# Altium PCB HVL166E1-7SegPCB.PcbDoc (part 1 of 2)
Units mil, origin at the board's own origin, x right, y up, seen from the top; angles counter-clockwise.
Board outline 2300 x 2421 mil, 2 copper layers (Top Layer, Bottom Layer), stack 62 mil thick; 193 components, 200 nets, 656 pads, 241 vias.
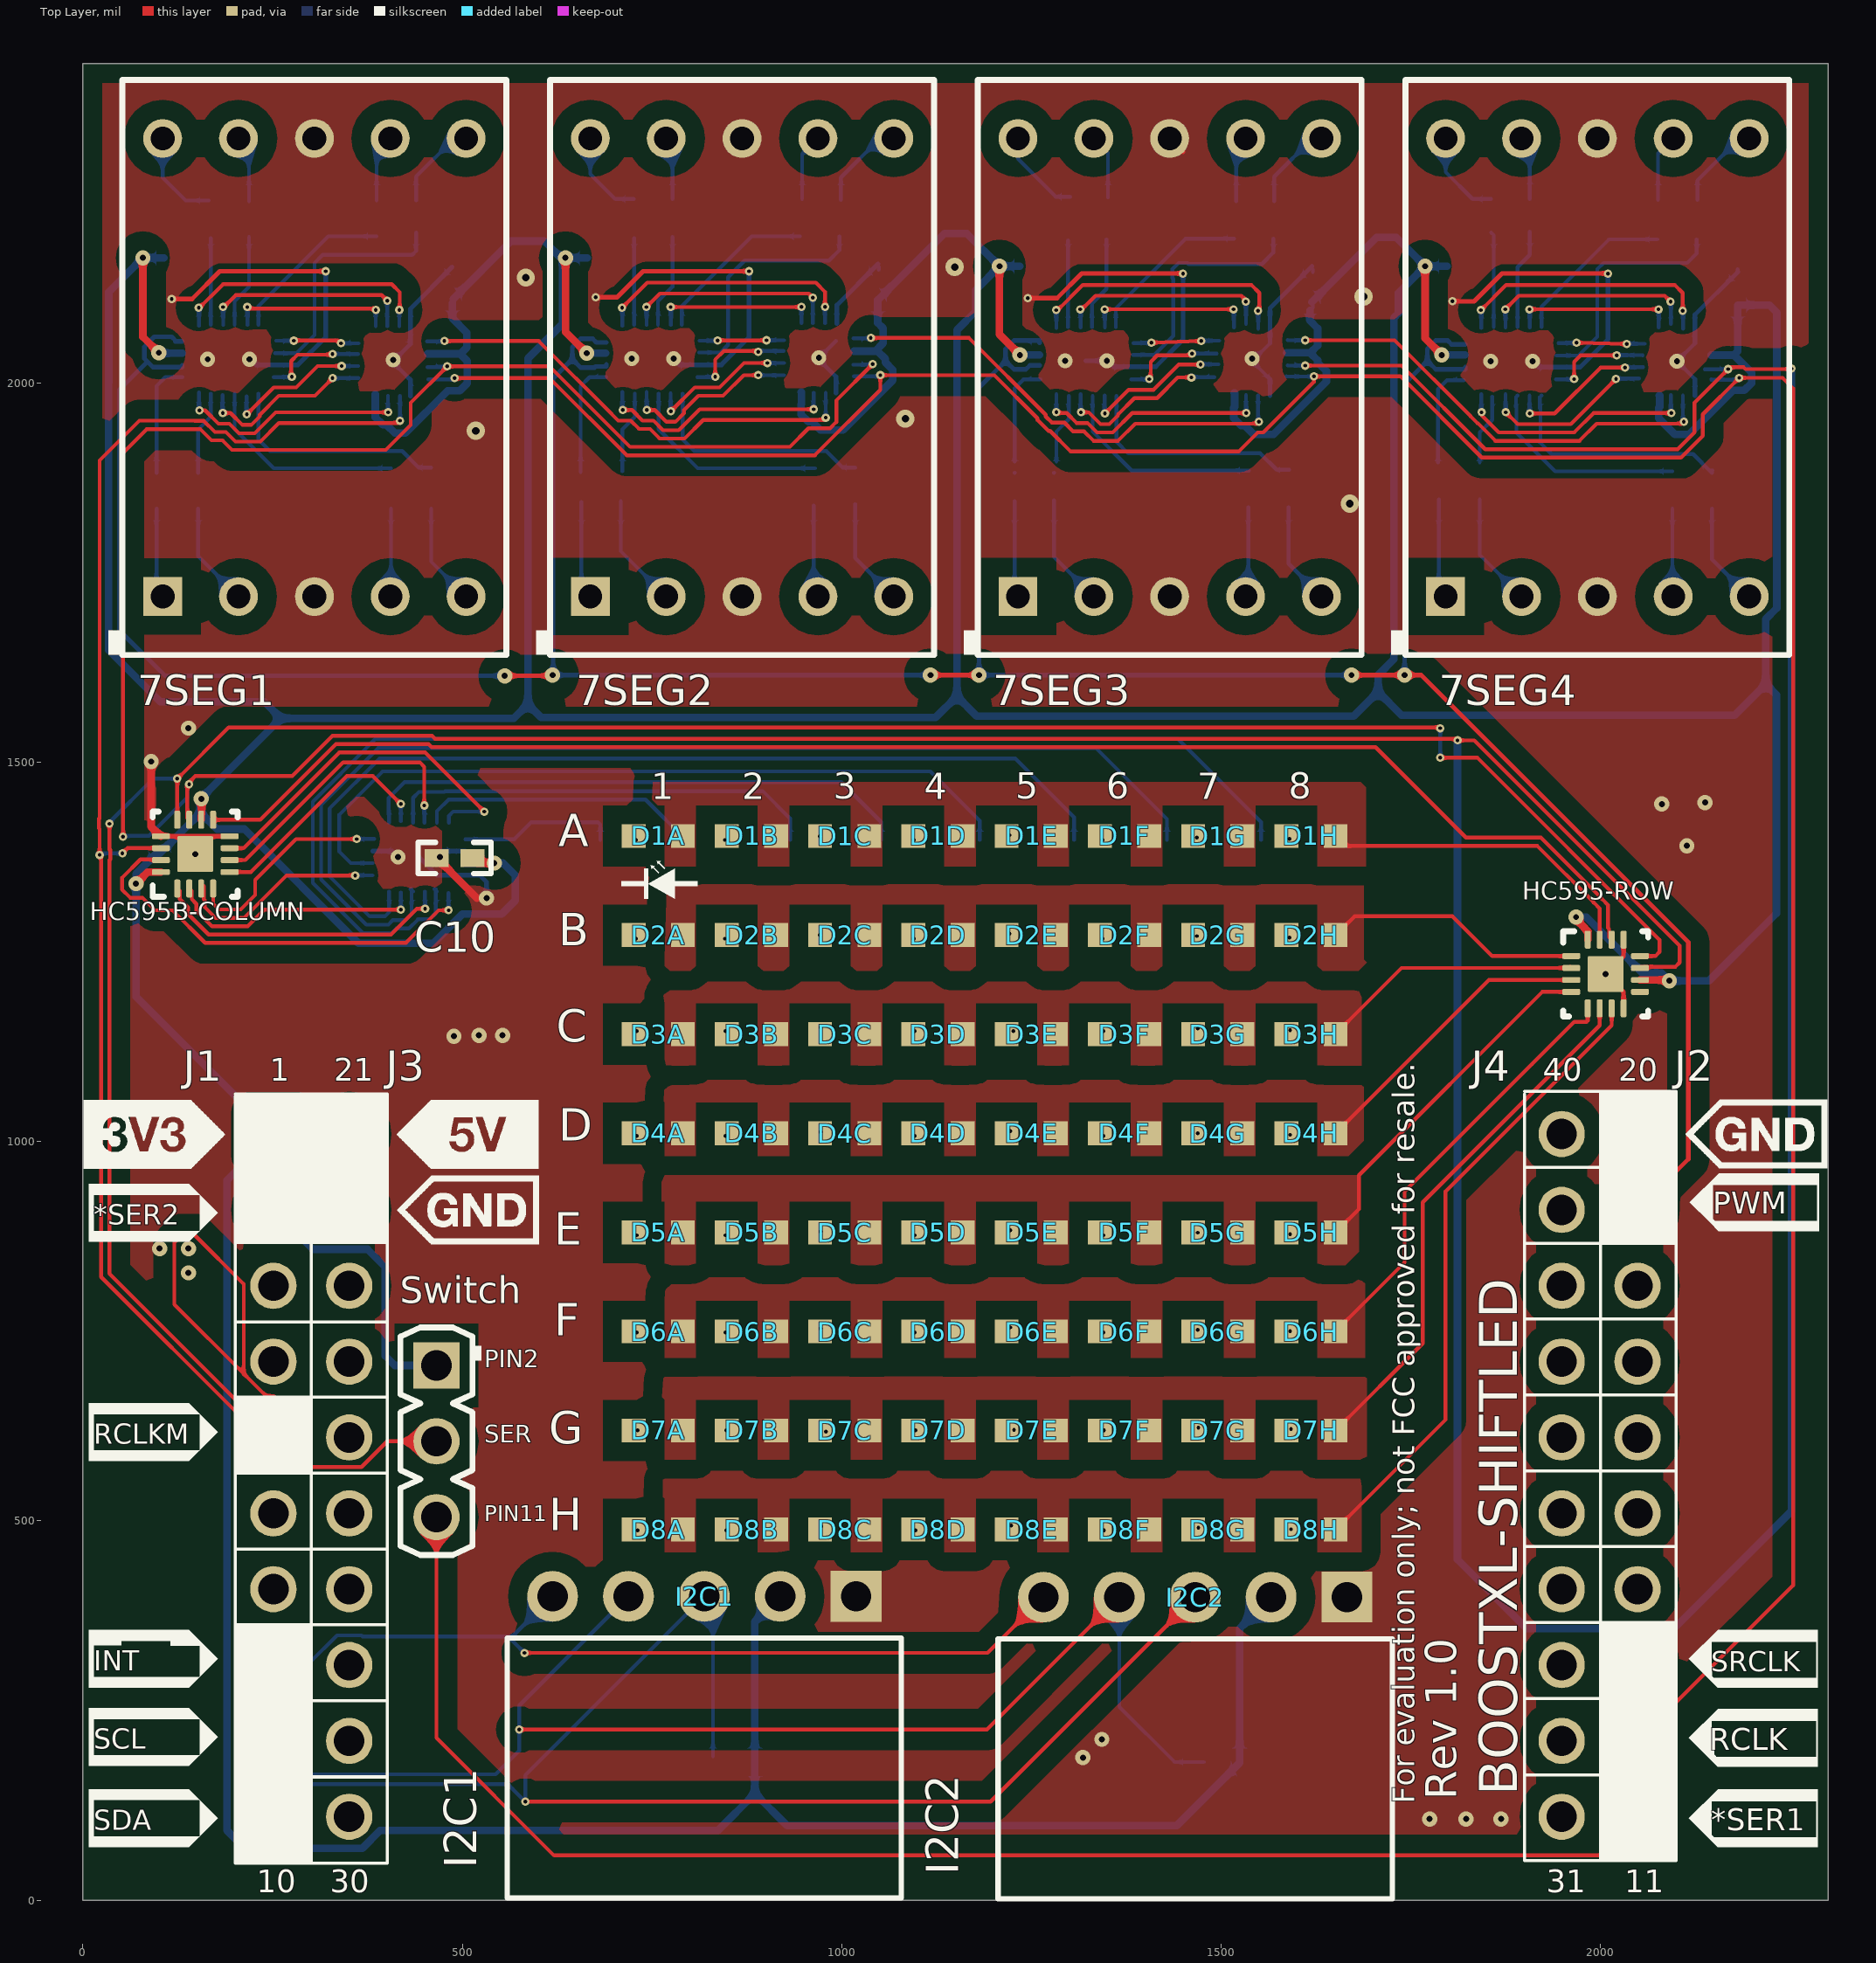
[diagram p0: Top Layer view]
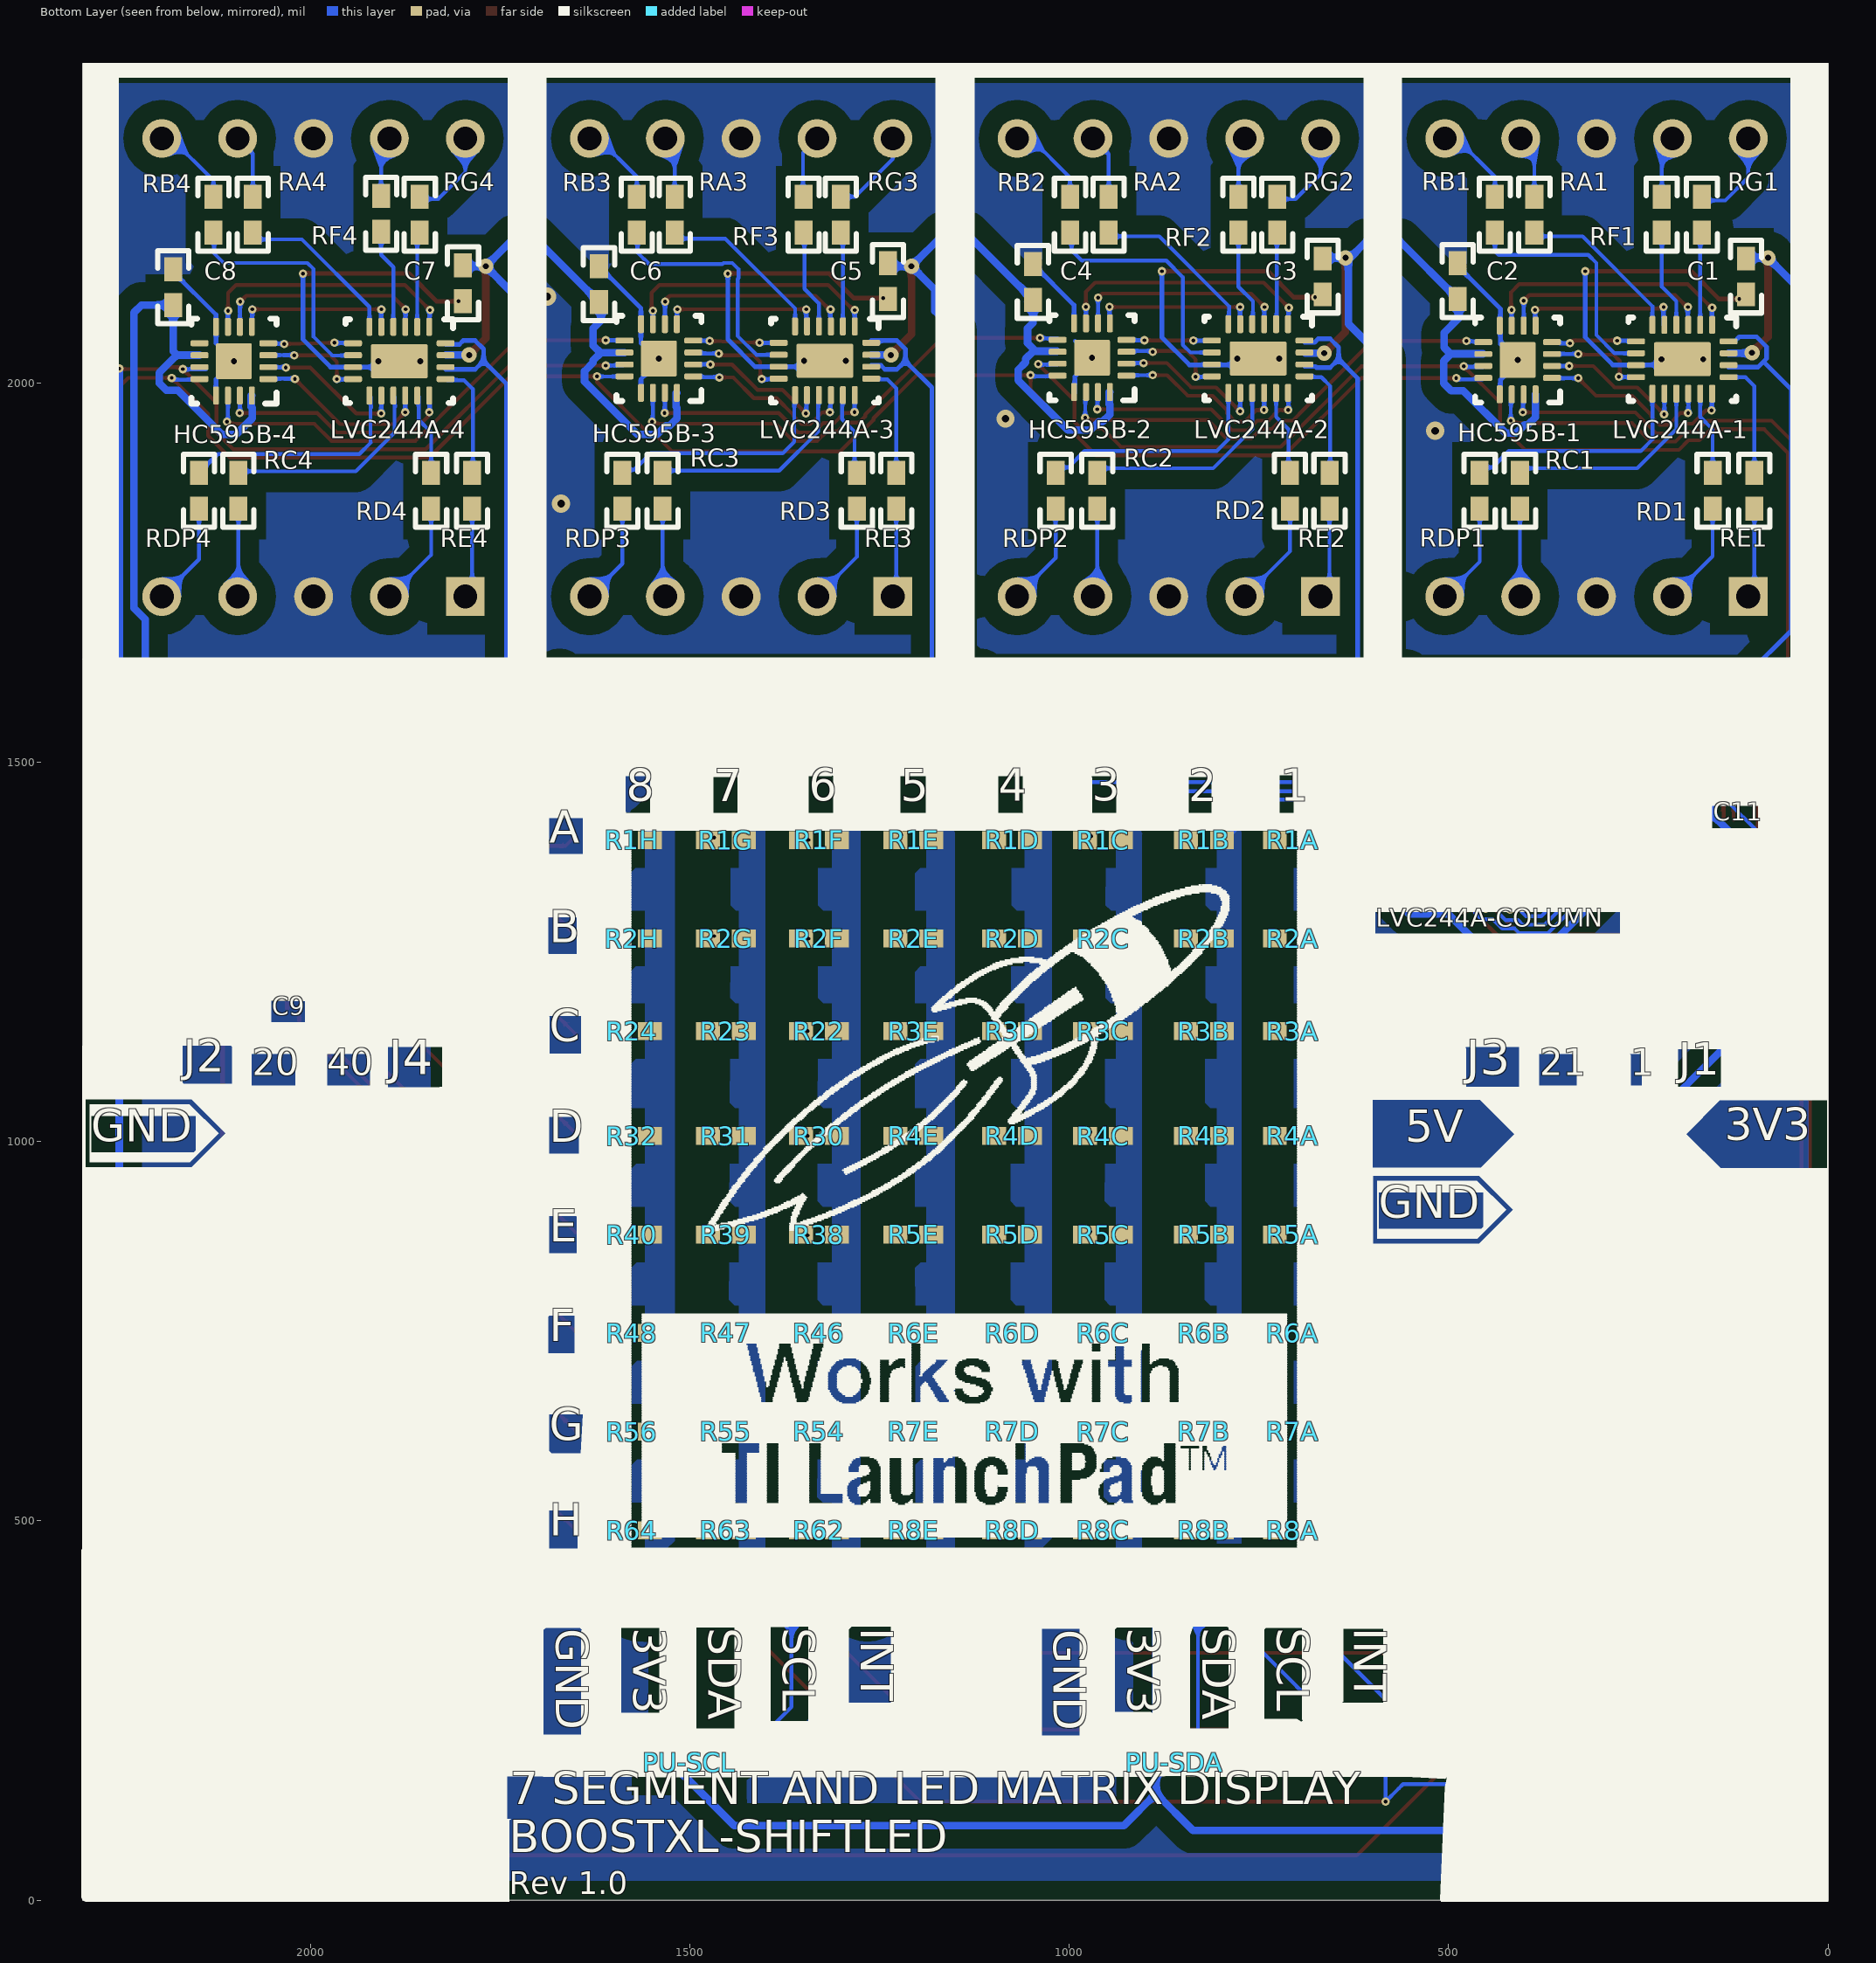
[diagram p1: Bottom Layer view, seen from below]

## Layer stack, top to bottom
Top Solder: solder mask 0.4, Solder Resist, Dk 3.5
Top Layer: signal copper 1.4
Dielectric1: core 59.2, FR-4, Dk 4.8
Bottom Layer: signal copper 1.4
Bottom Solder: solder mask 0.4, Solder Resist, Dk 3.5

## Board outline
0,0 0,2421 2300,2421 2300,0

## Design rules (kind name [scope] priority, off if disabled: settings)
AcuteAngle [All] p1: minimum=4.50000000000000E+0001 checktracksonly=FALSE
AssemblyTestPointUsage [All] p1: valid=2
BoardOutlineClearance BoardOutlineClearance_MountingHoles [OnCopper and InComponentClass('Mounting Holes')] p1: gap=40
BoardOutlineClearance BoardOutlineClearance_Poly [OnCopper and IsPoly] p2: gap=25
BoardOutlineClearance [OnCopper and Not InComponentClass('Logo') and not InComponentClass('FiducialMark') and not InRegion(1000,500,4000,800) and not InPoly] p3: gap=75
Clearance Clearance_Keepouts [((IsTrack Or IsArc) And Not InPoly) And IsFree and IsKeepOut vs ((IsTrack Or IsArc) And Not InPoly) And IsFree and IsKeepOut] p1: gap=0
Clearance Clearance_Poly [InPolygon] p2: gap=25
Clearance [All] p3: gap=6
ComponentClearance ComponentClearance_MountingHoles_FiducialMarks [InComponentClass('Mounting Holes') vs InComponentClass('FiducialMark')] p1: gap=50 collisioncheckmode=3 verticalgap=10 showdistances=FALSE
ComponentClearance ComponentClearance_Shunt [InComponentClass('Header') vs InComponentClass('Shunt')] p2: gap=0 collisioncheckmode=3 verticalgap=0 showdistances=FALSE
ComponentClearance ComponentClearance_Logo [InComponentClass('Logo')] p3: gap=50 collisioncheckmode=3 verticalgap=10 showdistances=FALSE
ComponentClearance ComponentClearance_ScrewToNut [(HasFootprint('NY PMS 440 0025 PH')) vs (HasFootprint('Keystone_1902C'))] p4: gap=5 collisioncheckmode=3 verticalgap=10 showdistances=FALSE
ComponentClearance ComponentClearance_MountingHoles [InComponentClass('Mounting Holes')] p5: gap=250 collisioncheckmode=3 verticalgap=100000 showdistances=FALSE
ComponentClearance ComponentClearance_SmallPassives [HasFootprint('0201*') or HasFootprint('0402*') or HasFootprint('0508') or HasFootprint('0603*') or HasFootprint('0612') or HasFootprint('0805*') or HasFootprint('0815*') or HasFootprint('0830*') or HasFootprint('1206*') or HasFootprint('1210*') or HasFootprint('1808*') or HasFootprint('1812*') or HasFootprint('1825*') or HasFootprint('2010*') or HasFootprint('2220*') or HasFootprint('2225*') or HasFootprint('2512*') or HasFootprint('2728*') or HasFootprint('3518*') vs HasFootprint('0201*') or HasFootprint('0402*') or HasFootprint('0508') or HasFootprint('0603*') or HasFootprint('0612') or HasFootprint('0805*') or HasFootprint('0815*') or HasFootprint('0830*') or HasFootprint('1206*') or HasFootprint('1210*') or HasFootprint('1808*') or HasFootprint('1812*') or HasFootprint('1825*') or HasFootprint('2010*') or HasFootprint('2220*') or HasFootprint('2225*') or HasFootprint('2512*') or HasFootprint('2728*') or HasFootprint('3518*')] p6: gap=14.96 collisioncheckmode=3 verticalgap=10 showdistances=FALSE
ComponentClearance ComponentClearance_THtoSMT [IsThruComponent vs IsSMTComponent] p7: gap=40 collisioncheckmode=3 verticalgap=30 showdistances=FALSE
ComponentClearance ComponentClearance_THtoTH [IsThruComponent vs IsThruComponent] p8: gap=30 collisioncheckmode=3 verticalgap=30 showdistances=FALSE
ComponentClearance [All] p9: gap=30 collisioncheckmode=3 verticalgap=10 showdistances=FALSE
DiffPairsRouting [All] p1: maxlimit=100 minlimit=10 mostfreqgap=10 toplayer_minwidth=15 toplayer_maxwidth=15 toplayer_prefwidth=15 bottomlayer_minwidth=15 bottomlayer_maxwidth=15 bottomlayer_prefwidth=15 maxuncoupledlength=1000
FabricationTestPointUsage TestPointUsage [All] p1: valid=2 allowmultiple=FALSE
FabricationTestpoint Testpoint [All] p1: side=3 testpointundercomponent=TRUE minsize=40 maxsize=100 preferedsize=60 minholesize=0 maxholesize=40 preferedholesize=32 testpointgrid=1 allowsidetop=TRUE allowsidebottom=TRUE usegrid=TRUE gridtolerance=0.01
FanoutControl Fanout_LCC [IsLCC] p1: bgadir=Out bgaviamode=Centered fanoutstyle=Auto fanoutdirection=Alternating viagrid=1 // Fanout_LCC (Default Rule)
FanoutControl Fanout_BGA [IsBGA] p2: bgadir=Out bgaviamode=Centered fanoutstyle=Auto fanoutdirection=Alternating viagrid=1 // Fanout_BGA (Default Rule)
FanoutControl Fanout_Default [All] p4: bgadir=Out bgaviamode=Centered fanoutstyle=Auto fanoutdirection=Alternating viagrid=1 // Fanout_Default (Default Rule)
FanoutControl Fanout_Small [(CompPinCount < 5)] p5: bgadir=Out bgaviamode=Centered fanoutstyle=Auto fanoutdirection=OutThenIn viagrid=1 // Fanout_Small (Default Rule)
HoleSize [All] p1: absolutevalues=TRUE maxlimit=251 minlimit=5 maxpercent=80.000 minpercent=20.000
MinimumAnnularRing MinimumAnnularRing_ThermalPadVias [IsVia and InAnyComponent] p1: minimumring=5.91
MinimumAnnularRing [All] p2: minimumring=5.91
MinimumSolderMaskSliver MinimumSolderMaskSliver_Logo [InComponentClass('Logo') vs InComponentClass('Logo')] p1: minsoldermaskwidth=0.7
MinimumSolderMaskSliver [All] p2: minsoldermaskwidth=3.94
PlaneConnect [All] p1: planeconnectstyle=Relief reliefexpansion=10 reliefentries=4 reliefconductorwidth=10 reliefairgap=10
PolygonConnect [All] p1: connectstyle=Direct reliefconductorwidth=10 reliefentries=4 polygonreliefangle="90 Angle" airgapwidth=10
RoutingVias ThermalPadVias [IsVia and InAnyComponent] p1: holewidth=7.87 width=19.68 viastyle="Through Hole" minholewidth=5 minwidth=11 maxholewidth=12.99 maxwidth=23.62
RoutingVias [All] p2: holewidth=16 width=34 viastyle="Through Hole" minholewidth=5 minwidth=11 maxholewidth=40 maxwidth=65
SilkToBoardRegionClearance [Not ((IsComment or IsDesignator) And (Hide <> 'False')) and not InRegion(1000,500,4000,800)] p1:
SilkToSilkClearance SilkToSilkClearance_Pb-FreeLogo [(HasFootprint('Pb-Free_Overlay_Medium') OR HasFootprint('Pb-Free_Overlay_Small')) vs (HasFootprint('Pb-Free_Overlay_Medium') OR HasFootprint('Pb-Free_Overlay_Small'))] p1: silktosilkclearance=0
SilkToSilkClearance [All] p2: silktosilkclearance=4
SilkToSolderMaskClearance SilkToComponentPadClearance [IsPad and InAnycomponent] p1: minsilkscreentomaskgap=5 clearancetoexposedcopper=TRUE
SilkToSolderMaskClearance "Silk to Solder Mask Opening" [All] p2: minsilkscreentomaskgap=4 clearancetoexposedcopper=FALSE
SolderMaskExpansion [All] p1: expansion=1.97
Width [All] p1: maxlimit=100 minlimit=2 preferedwidth=2 minimp=50.000000 maximp=50.000000 favimp=50.000000 checkconnectedcopper=TRUE
15 further rules are at their usual default settings.

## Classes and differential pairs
component class Header: Switch
component class HVL166E1-TI_Design_X1QFN: I2C1 I2C2 J3 J4 J? PU-SCL PU-SDA Switch
component class U_HVL166E1-7seg: 7SEG1 7SEG2 7SEG3 7SEG4 C1 C2 C3 C4 C5 C6 C7 C8 C? D? HC595B-1 HC595B-2 HC595B-3 HC595B-4 LVC244A-1 LVC244A-2 LVC244A-3 LVC244A-4 RA1 RA2 RA3 RA4 RB1 RB2 RB3 RB4 RC1 RC2 RC3 RC4 RD1 RD2 RD3 RD4 RDP1 RDP2 RDP3 RDP4 RE1 RE2 RE3 RE4 RF1 RF2 RF3 RF4 RG1 RG2 RG3 RG4
component class U_HVL166E1-LED_Screen: C9 C10 C11 C? D1 D1A D1B D1C D1D D1E D1F D1G D1H D2 D2A D2B D2C D2D D2E D2F D2G D2H D3 D3A D3B D3C D3D D3E D3F D3G D3H D4 D4A D4B D4C D4D D4E D4F D4G D4H D5 D5A D5B D5C D5D D5E D5F D5G D5H D6 D6A D6B D6C D6D D6E D6F D6G D6H D7 D7A D7B D7C D7D D7E D7F D7G D7H D8 D8A D8B D8C D8D D8E D8F D8G D8H HC595-ROW HC595B-COLUMN LVC244A-COLUMN R1 R1A R1B R1C R1D R1E R1F R1G R1H R2A R2B R2C R2D R2E R2F R2G R2H R3A R3B R3C R3D R3E R4A R4B R4C R4D R4E R5A R5B R5C R5D R5E R6A R6B R6C R6D R6E R7A R7B R7C R7D R7E R8A R8B R8C R8D R8E R22 R23 R24 R30 R31 R32 R38 R39 R40 R46 R47 R48 R54 R55 R56 R62 R63 R64 U11

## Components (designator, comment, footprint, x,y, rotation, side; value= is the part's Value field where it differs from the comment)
7SEG1 "LDS-HTC514RI" LDS-A514RI_Red 305.06,2020.45 r90 top
7SEG2 "LDS-HTC514RI" LDS-A514RI_Red 868.73,2020.45 r90 top
7SEG3 "LDS-HTC514RI" LDS-A514RI_Red 1432.4,2020.45 r90 top
7SEG4 "LDS-HTC514RI" LDS-A514RI_Red 1996.06,2020.45 r90 top
C1 "160R07X104KV4T" 0402_065 108,2140.39 r270 bottom
C2 "160R07X104KV4T" 0402_065 488,2134.39 r90 bottom
C3 "160R07X104KV4T" 0402_065 666,2140.39 r270 bottom
C4 "160R07X104KV4T" 0402_065 1048,2133.39 r90 bottom
C5 "160R07X104KV4T" 0402_065 1239,2134.39 r270 bottom
C6 "160R07X104KV4T" 0402_065 1619.83,2130.39 r90 bottom
C7 "160R07X104KV4T" 0402_065 1799,2131.39 r270 bottom
C8 "160R07X104KV4T" 0402_065 2181,2126.39 r90 bottom
C9 "160R07X104KV4T" 0402_065 2032,1222 r180 bottom
C10 "160R07X104KV4T" 0402_065 490,1374 r180 top
C11 "160R07X104KV4T" 0402_065 125,1380 r0 bottom
D1A "SML-311UTT86" SML-31_Red 758.29,1402.83 r0 top
D1B "SML-311UTT86" SML-31_Red 881.2,1402.83 r0 top
D1C "SML-311UTT86" SML-31_Red 1004.1,1402.83 r0 top
D1D "SML-311UTT86" SML-31_Red 1127,1402.83 r0 top
D1E "SML-311UTT86" SML-31_Red 1249.9,1402.83 r0 top
D1F "SML-311UTT86" SML-31_Red 1372.8,1402.83 r0 top
D1G "SML-311UTT86" SML-31_Red 1495.71,1402.83 r0 top
D1H "SML-311UTT86" SML-31_Red 1618.61,1402.83 r0 top
D2A "SML-311UTT86" SML-31_Red 758.29,1272.22 r0 top
D2B "SML-311UTT86" SML-31_Red 881.2,1272.22 r0 top
D2C "SML-311UTT86" SML-31_Red 1004.1,1272.22 r0 top
D2D "SML-311UTT86" SML-31_Red 1127,1272.22 r0 top
D2E "SML-311UTT86" SML-31_Red 1249.9,1272.22 r0 top
D2F "SML-311UTT86" SML-31_Red 1372.8,1272.22 r0 top
D2G "SML-311UTT86" SML-31_Red 1495.71,1272.22 r0 top
D2H "SML-311UTT86" SML-31_Red 1618.61,1272.22 r0 top
D3A "SML-311UTT86" SML-31_Red 758.29,1141.61 r0 top
D3B "SML-311UTT86" SML-31_Red 881.2,1141.61 r0 top
D3C "SML-311UTT86" SML-31_Red 1004.1,1141.61 r0 top
D3D "SML-311UTT86" SML-31_Red 1127,1141.61 r0 top
D3E "SML-311UTT86" SML-31_Red 1249.9,1141.61 r0 top
D3F "SML-311UTT86" SML-31_Red 1372.8,1141.61 r0 top
D3G "SML-311UTT86" SML-31_Red 1495.71,1141.61 r0 top
D3H "SML-311UTT86" SML-31_Red 1618.61,1141.61 r0 top
D4A "SML-311UTT86" SML-31_Red 758.29,1011 r0 top
D4B "SML-311UTT86" SML-31_Red 881.2,1011 r0 top
D4C "SML-311UTT86" SML-31_Red 1004.1,1011 r0 top
D4D "SML-311UTT86" SML-31_Red 1127,1011 r0 top
D4E "SML-311UTT86" SML-31_Red 1249.9,1011 r0 top
D4F "SML-311UTT86" SML-31_Red 1372.8,1011 r0 top
D4G "SML-311UTT86" SML-31_Red 1495.71,1011 r0 top
D4H "SML-311UTT86" SML-31_Red 1618.61,1011 r0 top
D5A "SML-311UTT86" SML-31_Red 758.29,880.39 r0 top
D5B "SML-311UTT86" SML-31_Red 881.2,880.39 r0 top
D5C "SML-311UTT86" SML-31_Red 1004.1,880.39 r0 top
D5D "SML-311UTT86" SML-31_Red 1127,880.39 r0 top
D5E "SML-311UTT86" SML-31_Red 1249.9,880.39 r0 top
D5F "SML-311UTT86" SML-31_Red 1372.8,880.39 r0 top
D5G "SML-311UTT86" SML-31_Red 1495.71,880.39 r0 top
D5H "SML-311UTT86" SML-31_Red 1618.61,880.39 r0 top
D6A "SML-311UTT86" SML-31_Red 758.29,749.78 r0 top
D6B "SML-311UTT86" SML-31_Red 881.2,749.78 r0 top
D6C "SML-311UTT86" SML-31_Red 1004.1,749.78 r0 top
D6D "SML-311UTT86" SML-31_Red 1127,749.78 r0 top
D6E "SML-311UTT86" SML-31_Red 1249.9,749.78 r0 top
D6F "SML-311UTT86" SML-31_Red 1372.8,749.78 r0 top
D6G "SML-311UTT86" SML-31_Red 1495.71,749.78 r0 top
D6H "SML-311UTT86" SML-31_Red 1618.61,749.78 r0 top
D7A "SML-311UTT86" SML-31_Red 758.29,619.17 r0 top
D7B "SML-311UTT86" SML-31_Red 881.2,619.17 r0 top
D7C "SML-311UTT86" SML-31_Red 1004.1,619.17 r0 top
D7D "SML-311UTT86" SML-31_Red 1127,619.17 r0 top
D7E "SML-311UTT86" SML-31_Red 1249.9,619.17 r0 top
D7F "SML-311UTT86" SML-31_Red 1372.8,619.17 r0 top
D7G "SML-311UTT86" SML-31_Red 1495.71,619.17 r0 top
D7H "SML-311UTT86" SML-31_Red 1618.61,619.17 r0 top
D8A "SML-311UTT86" SML-31_Red 758.29,488.57 r0 top
D8B "SML-311UTT86" SML-31_Red 881.2,488.57 r0 top
D8C "SML-311UTT86" SML-31_Red 1004.1,488.57 r0 top
D8D "SML-311UTT86" SML-31_Red 1127,488.57 r0 top
D8E "SML-311UTT86" SML-31_Red 1249.9,488.57 r0 top
D8F "SML-311UTT86" SML-31_Red 1372.8,488.57 r0 top
D8G "SML-311UTT86" SML-31_Red 1495.71,488.57 r0 top
D8H "SML-311UTT86" SML-31_Red 1618.61,488.57 r0 top
HC595-ROW "SN74HC595BRWNR" RWN0016A 2007,1221 r0 top
HC595B-1 "SN74HC595BRWNR" RWN0016A 409,2030.39 r0 bottom
HC595B-2 "SN74HC595BRWNR" RWN0016A 970,2033.39 r0 bottom
HC595B-3 "SN74HC595BRWNR" RWN0016A 1540.83,2032.39 r0 bottom
HC595B-4 "SN74HC595BRWNR" RWN0016A 2101,2028.83 r0 bottom
HC595B-COLUMN "SN74HC595BRWNR" RWN0016A 148,1379 r90 top
I2C1 "PPPC051LGBN-RC" CONN_PPPC051LGBN 819,184 r0 top
I2C2 "PPPC051LGBN-RC" CONN_PPPC051LGBN 1466,183 r0 top
J3 "SSQ-110-03-T-D" BoosterPack_40pin_J1J3 301,560 r180 bottom
J4 "SSQ-110-03-T-D" BoosterPack_40pin_J2J4 1999,560 r180 bottom
LVC244A-1 "SN74LVC244ARWPR" RWP0020A 192,2031.39 r270 bottom
LVC244A-2 "SN74LVC244ARWPR" RWP0020A 751,2032.39 r270 bottom
LVC244A-3 "SN74LVC244ARWPR" RWP0020A 1322,2029.39 r270 bottom
LVC244A-4 "SN74LVC244ARWPR" RWP0020A 1883,2028.83 r270 bottom
LVC244A-COLUMN "SN74LVC244ARWPR" RWP0020A 443,1375 r90 bottom
PU-SCL "CRCW06034K70JNEA" 0603 1501,182 r0 bottom
PU-SDA "CRCW06034K70JNEA" 0603 862,182 r0 bottom
R1A "CRCW0402750RJNED" 0402 705.48,1397.57 r180 bottom
R1B "CRCW0402750RJNED" 0402 822.41,1397.57 r180 bottom
R1C "CRCW0402750RJNED" 0402 955.52,1397.57 r180 bottom
R1D "CRCW0402750RJNED" 0402 1075.54,1397.57 r180 bottom
R1E "CRCW0402750RJNED" 0402 1205.56,1397.57 r180 bottom
R1F "CRCW0402750RJNED" 0402 1329.97,1397.57 r180 bottom
R1G "CRCW0402750RJNED" 0402 1452.41,1397.57 r180 bottom
R1H "CRCW0402750RJNED" 0402 1576.41,1397.57 r180 bottom
R2A "CRCW0402750RJNED" 0402 705.48,1267.57 r180 bottom
R2B "CRCW0402750RJNED" 0402 822.41,1267.57 r180 bottom
R2C "CRCW0402750RJNED" 0402 955.52,1267.57 r180 bottom
R2D "CRCW0402750RJNED" 0402 1075.54,1267.57 r180 bottom
R2E "CRCW0402750RJNED" 0402 1205.56,1267.57 r180 bottom
R2F "CRCW0402750RJNED" 0402 1329.97,1267.57 r180 bottom
R2G "CRCW0402750RJNED" 0402 1452.41,1267.57 r180 bottom
R2H "CRCW0402750RJNED" 0402 1576.41,1267.57 r180 bottom
R3A "CRCW0402750RJNED" 0402 705.48,1145.76 r180 bottom
R3B "CRCW0402750RJNED" 0402 822.41,1145.76 r180 bottom
R3C "CRCW0402750RJNED" 0402 955.52,1145.76 r180 bottom
R3D "CRCW0402750RJNED" 0402 1075.54,1145.76 r180 bottom
R3E "CRCW0402750RJNED" 0402 1205.56,1145.76 r180 bottom
R4A "CRCW0402750RJNED" 0402 705.48,1007.57 r180 bottom
R4B "CRCW0402750RJNED" 0402 822.41,1007.57 r180 bottom
R4C "CRCW0402750RJNED" 0402 955.52,1007.57 r180 bottom
R4D "CRCW0402750RJNED" 0402 1075.54,1007.57 r180 bottom
R4E "CRCW0402750RJNED" 0402 1205.56,1007.57 r180 bottom
R5A "CRCW0402750RJNED" 0402 705.48,877.57 r180 bottom
R5B "CRCW0402750RJNED" 0402 822.41,877.57 r180 bottom
R5C "CRCW0402750RJNED" 0402 955.52,877.57 r180 bottom
R5D "CRCW0402750RJNED" 0402 1075.54,877.57 r180 bottom
R5E "CRCW0402750RJNED" 0402 1205.56,877.57 r180 bottom
R6A "CRCW0402750RJNED" 0402 705.48,747.57 r180 bottom
R6B "CRCW0402750RJNED" 0402 822.41,747.57 r180 bottom
R6C "CRCW0402750RJNED" 0402 955.52,747.57 r180 bottom
R6D "CRCW0402750RJNED" 0402 1075.54,747.57 r180 bottom
R6E "CRCW0402750RJNED" 0402 1205.56,747.57 r180 bottom
R7A "CRCW0402750RJNED" 0402 705.48,617.57 r180 bottom
R7B "CRCW0402750RJNED" 0402 822.41,617.57 r180 bottom
R7C "CRCW0402750RJNED" 0402 955.52,617.57 r180 bottom
R7D "CRCW0402750RJNED" 0402 1075.54,617.57 r180 bottom
R7E "CRCW0402750RJNED" 0402 1205.56,617.57 r180 bottom
R8A "CRCW0402750RJNED" 0402 705.48,487.57 r180 bottom
R8B "CRCW0402750RJNED" 0402 822.41,487.57 r180 bottom
R8C "CRCW0402750RJNED" 0402 955.52,487.57 r180 bottom
R8D "CRCW0402750RJNED" 0402 1075.54,487.57 r180 bottom
R8E "CRCW0402750RJNED" 0402 1205.56,487.57 r180 bottom
R22 "CRCW0402750RJNED" 0402 1329.97,1145.76 r180 bottom
R23 "CRCW0402750RJNED" 0402 1452.41,1145.76 r180 bottom
R24 "CRCW0402750RJNED" 0402 1576.41,1145.76 r180 bottom
R30 "CRCW0402750RJNED" 0402 1329.97,1007.57 r180 bottom
R31 "CRCW0402750RJNED" 0402 1452.41,1007.57 r180 bottom
R32 "CRCW0402750RJNED" 0402 1576.41,1007.57 r180 bottom
R38 "CRCW0402750RJNED" 0402 1329.97,877.57 r180 bottom
R39 "CRCW0402750RJNED" 0402 1452.41,877.57 r180 bottom
R40 "CRCW0402750RJNED" 0402 1576.41,877.57 r180 bottom
R46 "CRCW0402750RJNED" 0402 1329.97,747.57 r180 bottom
R47 "CRCW0402750RJNED" 0402 1452.41,747.57 r180 bottom
R48 "CRCW0402750RJNED" 0402 1576.41,747.57 r180 bottom
R54 "CRCW0402750RJNED" 0402 1329.97,617.57 r180 bottom
R55 "CRCW0402750RJNED" 0402 1452.41,617.57 r180 bottom
R56 "CRCW0402750RJNED" 0402 1576.41,617.57 r180 bottom
R62 "CRCW0402750RJNED" 0402 1329.97,487.57 r180 bottom
R63 "CRCW0402750RJNED" 0402 1452.41,487.57 r180 bottom
R64 "CRCW0402750RJNED" 0402 1576.41,487.57 r180 bottom
RA1 "CRCW0402150RJNED" 0402 387,2222 r90 bottom
RA2 "CRCW0402150RJNED" 0402 948,2222 r90 bottom
RA3 "CRCW0402150RJNED" 0402 1520,2222 r90 bottom
RA4 "CRCW0402150RJNED" 0402 2076,2222 r90 bottom
RB1 "CRCW0402150RJNED" 0402 439,2222 r90 bottom
RB2 "CRCW0402150RJNED" 0402 999,2222 r90 bottom
RB3 "CRCW0402150RJNED" 0402 1570,2222 r90 bottom
RB4 "CRCW0402150RJNED" 0402 2128,2222 r90 bottom
RC1 "CRCW0402150RJNED" 0402 406,1858 r270 bottom
RC2 "CRCW0402150RJNED" 0402 963,1858 r270 bottom
RC3 "CRCW0402150RJNED" 0402 1536,1858 r270 bottom
RC4 "CRCW0402150RJNED" 0402 2095,1858 r270 bottom
RD1 "CRCW0402150RJNED" 0402 152,1858 r270 bottom
RD2 "CRCW0402150RJNED" 0402 709,1858 r270 bottom
RD3 "CRCW0402150RJNED" 0402 1280,1858 r270 bottom
RD4 "CRCW0402150RJNED" 0402 1841,1858 r270 bottom
RDP1 "CRCW0402150RJNED" 0402 459,1858 r270 bottom
RDP2 "CRCW0402150RJNED" 0402 1018,1858 r270 bottom
RDP3 "CRCW0402150RJNED" 0402 1589,1858 r270 bottom
RDP4 "CRCW0402150RJNED" 0402 2147,1858 r270 bottom
RE1 "CRCW0402150RJNED" 0402 97,1858 r270 bottom
RE2 "CRCW0402150RJNED" 0402 657,1858 r270 bottom
RE3 "CRCW0402150RJNED" 0402 1228,1858 r270 bottom
RE4 "CRCW0402150RJNED" 0402 1787,1858 r270 bottom
RF1 "CRCW0402150RJNED" 0402 219,2222 r90 bottom
RF2 "CRCW0402150RJNED" 0402 777,2222 r90 bottom
RF3 "CRCW0402150RJNED" 0402 1350,2222 r90 bottom
RF4 "CRCW0402150RJNED" 0402 1907,2223 r90 bottom
RG1 "CRCW0402150RJNED" 0402 166,2222 r90 bottom
RG2 "CRCW0402150RJNED" 0402 726,2222 r90 bottom
RG3 "CRCW0402150RJNED" 0402 1301,2222 r90 bottom
RG4 "CRCW0402150RJNED" 0402 1856,2222 r90 bottom
Switch "68001-403HLF" FCI_68001-403HLF 466,605 r270 top

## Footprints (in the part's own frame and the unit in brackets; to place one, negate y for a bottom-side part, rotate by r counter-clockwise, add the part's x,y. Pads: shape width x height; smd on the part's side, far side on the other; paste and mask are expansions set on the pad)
0402 [mm] "0402 from SM-752 data"
  rect 0.8x0.6 smd: 1(-0.6,0) 2(0.6,0)
  body extent -0.55,-0.3 0.55,0.3, height 0.6
0402_065 [mm] "0402"
  rect 0.8x0.6 smd: 1(-0.6,0) 2(0.6,0)
  silkscreen extent -1.22,-0.52 1.22,0.52, body extent -0.55,-0.3 0.55,0.3, height 0.65
0603 [mm] "0603 from SM-752 data"
  rect 1x0.95 smd: 1(-0.8,0) 2(0.8,0)
  body extent -0.87,-0.47 0.87,0.47, height 1
BoosterPack_40pin_J1J3 [mm] "Receptacle, 2.54mm, 10x2, TH"
  rrect6% 1.55x1.55 hole 1.02: 1(1.27,11.43)
  round 1.55 hole 1.02: 2(1.27,8.89) 3(1.27,6.35) 4(1.27,3.81) 5(1.27,1.27) 6(1.27,-1.27) 7(1.27,-3.81) 8(1.27,-6.35) 9(1.27,-8.89) 10(1.27,-11.43) 21(-1.27,11.43) 22(-1.27,8.89) 23(-1.27,6.35) 24(-1.27,3.81) 25(-1.27,1.27) 26(-1.27,-1.27) 27(-1.27,-3.81) 28(-1.27,-6.35) 29(-1.27,-8.89) 30(-1.27,-11.43)
  silkscreen extent -2.48,-12.95 2.48,12.95, body extent -2.48,-12.95 2.48,12.95, height 8.51
BoosterPack_40pin_J2J4 [mm] "Receptacle, 2.54mm, 10x2, TH"
  round 1.55 hole 1.02: 11(-1.27,-11.43) 12(-1.27,-8.89) 13(-1.27,-6.35) 14(-1.27,-3.81) 15(-1.27,-1.27) 16(-1.27,1.27) 17(-1.27,3.81) 18(-1.27,6.35) 19(-1.27,8.89) 20(-1.27,11.43) 31(1.27,-11.43) 32(1.27,-8.89) 33(1.27,-6.35) 34(1.27,-3.81) 35(1.27,-1.27) 36(1.27,1.27) 37(1.27,3.81) 38(1.27,6.35) 39(1.27,8.89) 40(1.27,11.43)
  silkscreen extent -2.48,-12.95 2.48,12.95, body extent -2.48,-12.95 2.48,12.95, height 8.51
CONN_PPPC051LGBN [mm] "SULLINS"
  rect 1.7x1.7 hole 1.016: 1(5.08,5.5)
  round 1.7 hole 1.016: 2(2.54,5.5) 3(0,5.5) 4(-2.54,5.5) 5(-5.08,5.5)
  silkscreen extent -6.6,-4.6 6.6,4.1, body extent -6.6,-4.6 6.6,5.7, height 2.56
FCI_68001-403HLF [mm] "Header, 2.54mm, 3x1, TH"
  rect 1.55x1.55 hole 1.02: 1(-2.54,0)
  round 1.55 hole 1.02: 2(0,0) 3(2.54,0)
  silkscreen extent -3.81,-1.21 3.81,1.5, body extent -3.81,-1.21 3.81,1.21, height 8.38
LDS-A514RI_Red [mm] "TH, 10-Leads, Body 19x12.6mm, Pitch 2.54mm"
  rect 1.3x1.3 hole 0.8: 1(-7.67,5.08)
  round 1.3 hole 0.8: 2(-7.67,2.54) 3(-7.67,0) 4(-7.67,-2.54) 5(-7.67,-5.08) 6(7.67,-5.08) 7(7.67,-2.54) 8(7.67,0) 9(7.67,2.54) 10(7.67,5.08)
  silkscreen extent -9.63,-6.42 9.62,6.9, body extent -9.68,-6.47 9.67,6.48, height 8.26
RWN0016A [mm] "SMD, 16-Leads, Body 2.5x2.5mm, Pitch 0.4mm"
  rrect50% 0.6x0.2 smd paste+0: 1(-1.15,0.6) 2(-1.15,0.2) 3(-1.15,-0.2) 4(-1.15,-0.6) 9(1.15,-0.6) 10(1.15,-0.2) 11(1.15,0.2) 12(1.15,0.6)
  rrect50% 0.2x0.6 smd paste+0: 5(-0.6,-1.15) 6(-0.2,-1.15) 7(0.2,-1.15) 8(0.6,-1.15) 13(0.6,1.15) 14(0.2,1.15) 15(-0.2,1.15) 16(-0.6,1.15)
  rrect8% 1.2x1.2 smd paste-0.035: 17(0,0)
  silkscreen extent -1.42,-1.42 1.42,1.42, body extent -1.28,-1.28 1.28,1.28, height 0.51
RWP0020A [mm] "QFN, 20-Leads, Body 2.5x3.3mm, Pitch 0.4mm"
  rrect50% 0.6x0.2 smd: 1(-1.15,1) 2(-1.15,0.6) 3(-1.15,0.2) 4(-1.15,-0.2) 5(-1.15,-0.6) 6(-1.15,-1) 11(1.15,-1) 12(1.15,-0.6) 13(1.15,-0.2) 14(1.15,0.2) 15(1.15,0.6) 16(1.15,1)
  rrect50% 0.2x0.6 smd: 7(-0.6,-1.55) 8(-0.2,-1.55) 9(0.2,-1.55) 10(0.6,-1.55) 17(0.6,1.55) 18(0.2,1.55) 19(-0.2,1.55) 20(-0.6,1.55)
  rrect9% 1.14x1.9 smd paste-1: 21(0,0)
  rrect12% 1.07x0.85 on Bottom Paste: ""(0,-0.525) ""(0,0.525)
  silkscreen extent -1.4,-1.8 1.4,1.8, body extent -1.25,-1.65 1.25,1.65, height 0.5
SML-31_Red [mm] "Rohm"
  rect 0.8x0.8 smd: 1(-0.825,0) 2(0.825,0)
  body extent -0.85,-0.45 0.85,0.45, height 0.91

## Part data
7SEG1 7SEG2 7SEG3 7SEG4: "LED, Red, TH"
C1 C2 C3 C4 C5 C6 C7 C8 C9 C10 C11: "CAP, CERM, 0.1 µF, 16 V, +/- 10%, X5R, 0402"
D1A D1B D1C D1D D1E D1F D1G D1H D2A D2B D2C D2D D2E D2F D2G D2H D3A D3B D3C D3D D3E D3F D3G D3H D4A D4B D4C D4D D4E D4F D4G D4H D5A D5B D5C D5D D5E D5F D5G D5H D6A D6B D6C D6D D6E D6F D6G D6H D7A D7B D7C D7D D7E D7F D7G D7H D8A D8B D8C D8D D8E D8F D8G D8H: "LED, Red, SMD"
HC595-ROW HC595B-1 HC595B-2 HC595B-3 HC595B-4 HC595B-COLUMN: "8-Bit Shift Registers With 3-State Output Register, RWN0016A"
I2C1 I2C2: "Receptacle, 100mil, 5x1, Gold, R/A, TH"
J3: library part BoosterPack_40pin_J1J3, "Receptacle, 2.54mm, 10x2, Tin, TH"
J4: library part BoosterPack_40pin_J2J4, "Receptacle, 2.54mm, 10x2, Tin, TH"
LVC244A-1 LVC244A-2 LVC244A-3 LVC244A-4 LVC244A-COLUMN: "Octal Buffer or Driver With 3-State Output, RWP0020A"
PU-SCL PU-SDA: "RES, 4.7 k, 5%, 0.1 W, 0603"
R1A R1B R1C R1D R1E R1F R1G R1H R2A R2B R2C R2D R2E R2F R2G R2H R3A R3B R3C R3D R3E R4A R4B R4C R4D R4E R5A R5B R5C R5D R5E R6A R6B R6C R6D R6E R7A R7B R7C R7D R7E R8A R8B R8C R8D R8E R22 R23 R24 R30 R31 R32 R38 R39 R40 R46 R47 R48 R54 R55 R56 R62 R63 R64: "RES, 750, 5%, 0.063 W, 0402"
RA1 RA2 RA3 RA4 RB1 RB2 RB3 RB4 RC1 RC2 RC3 RC4 RD1 RD2 RD3 RD4 RDP1 RDP2 RDP3 RDP4 RE1 RE2 RE3 RE4 RF1 RF2 RF3 RF4 RG1 RG2 RG3 RG4: "RES, 150, 5%, 0.063 W, 0402"
Switch: "Header, 2.54mm, 3x1, Tin, TH"

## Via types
v1: diameter 11, hole 5, Top Layer to Bottom Layer, 172 vias
v2: diameter 20, hole 8, Top Layer to Bottom Layer, 36 vias
v3: diameter 19.68, hole 7.87, Top Layer to Bottom Layer, 27 vias
v4: diameter 24, hole 10, Top Layer to Bottom Layer, 6 vias

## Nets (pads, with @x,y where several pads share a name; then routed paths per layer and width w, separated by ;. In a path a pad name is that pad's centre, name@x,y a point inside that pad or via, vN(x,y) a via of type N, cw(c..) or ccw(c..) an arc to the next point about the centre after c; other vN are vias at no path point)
1A1A: HC595B-1.7 LVC244A-1.1 | length 353.2
  Top Layer w5: v1@151.62,2097.19 184.82,2130.39 407,2130.39 417.62,2119.77 v1@417.62,2096.21
  Bottom Layer w5: LVC244A-1.1@153,2075.45 v1@153,2098.82 ; HC595B-1.7@417,2074.79 v1(417,2096.39)
  Bottom Layer w10: v1(152.62,2099.19) v1@153,2098.82
1A1B: HC595B-2.7 LVC244A-2.1 | length 351.6
  Top Layer w5: v1(710.62,2099.19) 743.82,2132.39 966,2132.39 978,2120.39 v1(978,2100.39)
  Bottom Layer w5: LVC244A-2.1@711,2075.45 v1@711,2098.82 ; HC595B-2.7@978,2078.79 v1(978,2100.39)
  Bottom Layer w10: v1(710.62,2099.19) v1@711,2098.82
1A1C: HC595B-4.7 LVC244A-4.1 | length 355.5
  Top Layer w5: v1(1842.62,2096.19) 1875.82,2129.39 2098,2129.39 2108.62,2118.77 v1(2108.62,2095.21)
  Bottom Layer w5: LVC244A-4.1@1843,2072.45 v1@1843,2095.82 ; HC595B-4.7@2109,2071.47 v1@2109,2094.83
  Bottom Layer w10: v1(1842.62,2096.19) v1@1843,2095.82 ; v1(2108.62,2095.21) v1@2109,2094.83
1A1D: HC595B-3.7 LVC244A-3.1 | length 355.5
  Top Layer w5: v1@1284.62,2096.19 1317.82,2129.39 1540,2129.39 1550.62,2118.77 v1@1550.62,2095.21
  Bottom Layer w5: LVC244A-3.1@1283,2072.45 v1@1283,2095.82 ; HC595B-3.7@1549,2071.47 v1@1549,2094.83
  Bottom Layer w10: v1(1282.62,2096.19) v1@1283,2095.82 ; v1(1548.62,2095.21) v1@1549,2094.83
1A2A: HC595B-1.6 LVC244A-1.3 | length 286.2
  Top Layer w5: v1@183.62,2098.19 201.51,2116.08 393.75,2116.08 v1@401.62,2108.21
  Bottom Layer w5: LVC244A-1.3@185,2076.45 v1@185,2099.82 ; HC595B-1.6@401,2074.79 v1(401,2108.39)
  Bottom Layer w10: v1(184.62,2100.19) v1@185,2099.82
1A2B: HC595B-2.6 LVC244A-2.3 | length 286.6
  Top Layer w5: v1(742.62,2100.19) 760.51,2118.08 956.31,2118.08 v1(962,2112.39)
  Bottom Layer w5: LVC244A-2.3@743,2076.45 v1@743,2099.82 ; HC595B-2.6@962,2078.79 v1(962,2112.39)
  Bottom Layer w10: v1(742.62,2100.19) v1@743,2099.82
1A2C: HC595B-4.6 LVC244A-4.3 | length 282.1
  Top Layer w5: v1(1874.62,2097.19) 1892.51,2115.08 2084.75,2115.08 v1(2092.62,2107.21)
  Bottom Layer w5: LVC244A-4.3@1875,2073.45 v1@1875,2096.82 ; HC595B-4.6@2093,2077.83 v1@2093,2106.83
  Bottom Layer w10: v1(1874.62,2097.19) v1@1875,2096.82 ; v1(2092.62,2107.21) v1@2093,2106.83
1A2D: HC595B-3.6 LVC244A-3.3 | length 282.1
  Top Layer w5: v1@1316.62,2097.19 1334.51,2115.08 1526.75,2115.08 v1@1534.62,2107.21
  Bottom Layer w5: LVC244A-3.3@1315,2073.45 v1@1315,2096.82 ; HC595B-3.6@1533,2077.83 v1@1533,2106.83
  Bottom Layer w10: v1(1314.62,2097.19) v1@1315,2096.82 ; v1(1532.62,2107.21) v1@1533,2106.83
1A3A: HC595B-1.5 LVC244A-1.5 | length 215
  Top Layer w5: v1@215.62,2098.19 v1@385.61,2098.19
  Bottom Layer w5: LVC244A-1.5@217,2076.45 v1@217,2099.82 ; HC595B-1.5@386,2075.29 v1(386,2096.39)
  Bottom Layer w10: v1(216.62,2100.19) v1@217,2099.82
1A3B: HC595B-2.5 LVC244A-2.5 | length 217.2
  Top Layer w5: v1(774.62,2100.19) v1@946.8,2100.19
  Bottom Layer w5: LVC244A-2.5@775,2076.45 v1@775,2099.82 ; HC595B-2.5@947,2079.29 v1(947,2100.39)
  Bottom Layer w10: v1(774.62,2100.19) v1@775,2099.82
1A3C: HC595B-4.5 LVC244A-4.5 | length 217.8
  Top Layer w5: v1(1906.62,2097.19) v1(2076.62,2097.21)
  Bottom Layer w5: LVC244A-4.5@1907,2073.45 v1@1907,2096.82 ; HC595B-4.5@2077,2073.47 v1@2077,2096.83
  Bottom Layer w10: v1(1906.62,2097.19) v1@1907,2096.82 ; v1(2076.62,2097.21) v1@2077,2096.83
1A3D: HC595B-3.5 LVC244A-3.5 | length 217.8
  Top Layer w5: v1@1348.62,2097.19 v1@1518.61,2097.19
  Bottom Layer w5: LVC244A-3.5@1347,2073.45 v1@1347,2096.82 ; HC595B-3.5@1517,2073.47 v1@1517,2096.83
  Bottom Layer w10: v1(1346.62,2097.19) v1@1347,2096.82 ; v1(1516.62,2097.21) v1@1517,2096.83
1A4A: HC595B-1.4 LVC244A-1.7 | length 111.8
  Top Layer w0: v1@277.38,2054.19 v1@278.51,2055.33
  Top Layer w5: v1@278.38,2056.19 336.2,2056.19 v1(340,2052.39)
  Bottom Layer w5: LVC244A-1.7@254.64,2055.82 v1(278,2055.82) ; v1(340,2052.39) HC595B-1.4@363.1,2052.39
  Bottom Layer w10: v1(278,2055.82) v1@278.38,2056.19
1A4B: HC595B-2.4 LVC244A-2.7 | length 113
  Top Layer w0: v1(836.38,2056.19) v1@837.51,2057.33
  Top Layer w5: v1(836.38,2056.19) v1@900.8,2056.19
  Bottom Layer w5: LVC244A-2.7@812.64,2055.82 v1@836,2055.82 ; v1(901,2056.39) HC595B-2.4@924.1,2056.39
  Bottom Layer w10: v1@836,2055.82 v1(836.38,2056.19)
1A4C: HC595B-4.4 LVC244A-4.7 | length 115.7
  Top Layer w0: v1(1968.38,2053.19) v1@1969.51,2054.33
  Top Layer w5: v1(1968.38,2053.19) v1(2034.62,2051.45)
  Bottom Layer w5: LVC244A-4.7@1944.64,2052.82 v1@1968,2052.82 ; v1@2035,2051.83 HC595B-4.4@2058.36,2051.83
  Bottom Layer w10: v1@1968,2052.82 v1(1968.38,2053.19) ; v1(2034.62,2051.45) v1@2035,2051.83
1A4D: HC595B-3.4 LVC244A-3.7 | length 113.1
  Top Layer w0: v1@1410.38,2053.19 v1@1411.51,2054.33
  Top Layer w5: v1@1410.38,2053.19 v1(1474,2055.39)
  Bottom Layer w5: LVC244A-3.7@1384.64,2052.82 v1@1408,2052.82 ; v1@1474.38,2055.77 HC595B-3.4@1497.74,2055.77
  Bottom Layer w10: v1@1408,2052.82 v1(1408.38,2053.19) ; v1(1474,2055.39) v1@1474.38,2055.77
1Y1A: LVC244A-1.17 RE1.1 | length 153.2
  Bottom Layer w5: RE1.1@97,1881.62 97,1996 108.77,2007.77 LVC244A-1.17@130.98,2007.77
1Y1B: LVC244A-2.17 RE2.1 | length 152.2
  Bottom Layer w5: RE2.1@656,1882.62 656,1996 667.77,2007.77 LVC244A-2.17@689.98,2007.77
1Y1C: LVC244A-4.17 RE4.1 | length 135.2
  Bottom Layer w5: RE4.1@1786,1895.62 1786,1992 1797.77,2003.77 LVC244A-4.17@1819.98,2003.77
1Y1D: LVC244A-3.17 RE3.1 | length 135.6
  Bottom Layer w5: RE3.1@1228,1881.62 RE3.1@1228,1882 ; RE3.1@1228,1896.62 1228,1993 1239.77,2004.77 LVC244A-3.17@1261.98,2004.77
1Y2A: LVC244A-1.15 RD1.1 | length 111.3
  Bottom Layer w5: RD1.1@152,1881.62 152,1939 168.38,1955.38 LVC244A-1.15@168.38,1986.11
1Y2B: LVC244A-2.15 RD2.1 | length 109.3
  Bottom Layer w5: RD2.1@711,1883.62 711,1939 727.38,1955.38 LVC244A-2.15@727.38,1986.11
1Y2C: LVC244A-4.15 RD4.1 | length 93.3
  Bottom Layer w5: RD4.1@1841,1895.62 1841,1935 1857.38,1951.38 LVC244A-4.15@1857.38,1982.11
1Y2D: LVC244A-3.15 RD3.1 | length 93.7
  Bottom Layer w5: RD3.1@1280,1881.62 RD3.1@1280,1882 ; RD3.1@1283,1896.62 1283,1936 1299.38,1952.38 LVC244A-3.15@1299.38,1983.11
1Y3A: LVC244A-1.13 RC1.1 | length 274.4
  Bottom Layer w5: LVC244A-1.13@199.87,1986.11 199.87,1939.13 251.38,1887.62 RC1.1@406,1887.62
1Y3B: LVC244A-2.13 RC2.1 | length 274.4
  Bottom Layer w5: LVC244A-2.13@758.87,1986.11 758.87,1939.13 810.38,1887.62 RC2.1@965,1887.62
1Y3C: LVC244A-4.13 RC4.1 | length 277.1
  Bottom Layer w5: LVC244A-4.13@1890.87,1983.56 1888.87,1981.56 1888.87,1968.24 1889.38,1967.74 1889.38,1935.63 1888.87,1935.13 1940.38,1883.62 RC4.1@2095,1883.62
1Y3D: LVC244A-3.13 RC3.1 | length 274.4
  Bottom Layer w5: LVC244A-3.13@1330.87,1983.11 1330.87,1936.13 1382.38,1884.62 RC3.1@1537,1884.62
1Y4A: LVC244A-1.11 RDP1.1 | length 303.4
  Bottom Layer w5: LVC244A-1.11@231.37,1986.11 231.37,1925.63 246.63,1910.37 420.71,1910.37 442.46,1888.62 RDP1.1@459,1888.62
1Y4B: LVC244A-2.11 RDP2.1 | length 303.4
  Bottom Layer w5: LVC244A-2.11@790.37,1986.11 790.37,1925.63 805.63,1910.37 979.71,1910.37 1001.46,1888.62 RDP2.1@1018,1888.62
1Y4C: LVC244A-4.11 RDP4.1 | length 310.5
  Bottom Layer w5: LVC244A-4.11@1922.37,1983.56 1920.37,1981.56 1920.37,1966.88 1921,1966.24 1921,1922.26 1920.37,1921.63 1935.63,1906.37 2122.25,1906.37 RDP4.1@2144,1884.62 ; RDP4.1@2147,1881.62 RDP4.1@2144,1884.62 ; RDP4.1@2148,1884.62 RDP4.1@2144,1884.62
1Y4D: LVC244A-3.11 RDP3.1 | length 303.4
  Bottom Layer w5: LVC244A-3.11@1362.37,1983.11 1362.37,1922.63 1377.63,1907.37 1551.71,1907.37 1573.46,1885.62 RDP3.1@1590,1885.62
2A1A: HC595B-1.3 LVC244A-1.10 | length 140
  Top Layer w5: v1@274.38,2006.19 274.38,2028.93 282.9,2037.45 v1@330.62,2037.45
  Bottom Layer w5: LVC244A-1.10@251.64,2007.82 v1@275,2007.82 ; v1(329,2038.39) HC595B-1.3@362.6,2038.39
  Bottom Layer w10: v1@275,2007.82 v1(275.38,2008.19)
2A1B: HC595B-2.3 LVC244A-2.10 | length 141.6
  Top Layer w5: v1(833.38,2008.19) 833.38,2030.93 844.84,2042.39 v1@890,2042.39
  Bottom Layer w5: LVC244A-2.10@809.64,2007.82 v1@833,2007.82 ; v1@890,2042.39 HC595B-2.3@923.6,2042.39
  Bottom Layer w10: v1@833,2007.82 v1(833.38,2008.19)
  other v1: 890,2041
2A1C: HC595B-4.3 LVC244A-4.10 | length 140.7
  Top Layer w5: v1(1965.38,2005.19) 1965.38,2027.93 1973.9,2036.45 v1(2021.62,2036.45)
  Bottom Layer w5: LVC244A-4.10@1941.64,2004.82 v1@1965,2004.82 ; v1@2022,2036.83 HC595B-4.3@2055.72,2036.71
  Bottom Layer w10: v1@1965,2004.82 v1(1965.38,2005.19) ; v1(2021.62,2036.45) v1@2022,2036.83
2A1D: HC595B-3.3 LVC244A-3.10 | length 134.5
  Top Layer w5: v1@1407.38,2005.19 1407.38,2027.93 1415.9,2036.45 v1@1459.45,2036.45
  Bottom Layer w5: LVC244A-3.10@1381.64,2004.82 v1@1405,2004.82 ; v1(1462,2039) HC595B-3.3@1494.29,2039
  Bottom Layer w10: v1@1405,2004.82 v1(1405.38,2005.19)
2A2A: HC595B-1.2 LVC244A-1.12 | length 197.1
  Top Layer w5: v1(216,1958.82) 251.38,1994.19 281.18,1994.19 309.37,2022.39 v1(341,2022.39)
  Bottom Layer w5: v1@215.62,1959.19 LVC244A-1.12@215.62,1982.56 ; v1(341,2022.39) HC595B-1.2@362.85,2022.39
  Bottom Layer w10: v1@215.62,1959.19 v1(216,1958.82)
2A2B: HC595B-2.2 LVC244A-2.12 | length 199.1
  Top Layer w5: v1(775,1962.82) 806.38,1994.19 839.18,1994.19 871.37,2026.39 v1(902,2026.39)
  Bottom Layer w5: v1@774.62,1963.19 LVC244A-2.12@774.62,1986.56 ; v1(902,2026.39) HC595B-2.2@923.85,2026.39
  Bottom Layer w10: v1@774.62,1963.19 v1(775,1962.82)
2A2C: HC595B-4.2 LVC244A-4.12 | length 198.5
  Top Layer w5: v1(1907,1959.82) 1939.8,1959.82 2000.44,2020.45 v1(2032.62,2020.45)
  Bottom Layer w5: v1@1906.62,1960.19 LVC244A-4.12@1906.62,1983.56 ; v1@2033,2020.83 HC595B-4.2@2056.36,2020.83
  Bottom Layer w10: v1@1906.62,1960.19 v1(1907,1959.82) ; v1(2032.62,2020.45) v1@2033,2020.83
2A2D: HC595B-3.2 LVC244A-3.12 | length 200.5
  Top Layer w5: v1(1347,1959.82) 1378.38,1991.19 1411.18,1991.19 1444.37,2024.39 v1(1473,2024.39)
  Bottom Layer w5: v1@1346.62,1960.19 LVC244A-3.12@1346.62,1983.56 ; v1@1473.38,2024.77 HC595B-3.2@1496.74,2024.77
  Bottom Layer w10: v1@1346.62,1960.19 v1(1347,1959.82) ; v1(1473,2024.39) v1@1473.38,2024.77
2A3A: HC595B-1.1 LVC244A-1.14 | length 235.8
  Top Layer w5: v1(184.38,1960.44) 194.58,1960.44 210.2,1944.82 221.8,1944.82 233.18,1956.2 233.18,1958.18 258.19,1983.19 305.8,1983.19 v1(329,2006.39)
  Bottom Layer w5: v1@184,1960.82 LVC244A-1.14@184,1984.18 ; v1(329,2006.39) HC595B-1.1@363.1,2006.39
  Bottom Layer w10: v1@184,1960.82 v1(184.38,1960.44)
2A3B: HC595B-2.1 LVC244A-2.14 | length 238.9
  Top Layer w5: v1(743.38,1964.44) 753.58,1964.44 769.2,1948.82 780.8,1948.82 792.18,1960.2 792.18,1964.18 811.19,1983.19 843.73,1983.19 870.93,2010.39 v1(890,2010.39)
  Bottom Layer w5: v1@743,1964.82 LVC244A-2.14@743,1988.18 ; v1(890,2010.39) HC595B-2.1@924.1,2010.39
  Bottom Layer w10: v1@743,1964.82 v1(743.38,1964.44)
2A3C: HC595B-4.1 LVC244A-4.14 | length 230.7
  Top Layer w5: v1(1875.38,1961.44) 1891,1945.82 1960.98,1945.82 v1(2020.62,2005.45)
  Bottom Layer w5: v1@1875,1961.82 LVC244A-4.14@1875,1985.18 ; v1@2021,2005.83 HC595B-4.1@2050.8,2005.83
  Bottom Layer w10: v1@1875,1961.82 v1(1875.38,1961.44) ; v1(2020.62,2005.45) v1@2021,2005.83
2A3D: HC595B-3.1 LVC244A-3.14 | length 232.7
  Top Layer w5: v1(1315.38,1961.44) 1325.58,1961.44 1341.2,1945.82 1352.8,1945.82 1364.18,1957.2 1364.18,1958.61 1385.76,1980.19 1415.73,1980.19 1442.93,2007.39 v1(1461,2007.39)
  Bottom Layer w5: v1@1315,1961.82 LVC244A-3.14@1315,1985.18 ; v1@1461.38,2007.77 HC595B-3.1@1491.18,2007.77
  Bottom Layer w10: v1@1315,1961.82 v1(1315.38,1961.44) ; v1(1461,2007.39) v1@1461.38,2007.77
2A4A: HC595B-1.15 LVC244A-1.16 | length 318.7
  Top Layer w5: v1(153.38,1964.01) 161,1964.01 178.58,1946.44 193.02,1946.44 205.64,1933.82 226.36,1933.82 253.99,1961.45 v1(402.38,1961.45)
  Bottom Layer w5: v1@153,1964.39 LVC244A-1.16@153,1987.75 ; v1@402,1961.39 HC595B-1.15@402,1983.24
  Bottom Layer w10: v1@153,1964.39 v1(153.38,1964.01)
2A4B: HC595B-2.15 LVC244A-2.16 | length 319.8
  Top Layer w5: v1(711.38,1964.44) 723.58,1964.44 737.58,1950.44 752.02,1950.44 764.64,1937.82 785.36,1937.82 812.93,1965.39 v1(963,1965.39)
  Bottom Layer w5: v1@711,1964.82 LVC244A-2.16@711,1988.18 ; v1(963,1965.39) HC595B-2.15@963,1987.24
  Bottom Layer w10: v1@711,1964.82 v1(711.38,1964.44)
2A4C: HC595B-4.15 LVC244A-4.16 | length 321.7
  Top Layer w5: v1(1843.38,1961.44) 1843.38,1957.62 1866.18,1934.82 1965.54,1934.82 1991.18,1960.45 v1(2093.38,1960.45)
  Bottom Layer w5: v1@1843,1961.82 LVC244A-4.16@1843,1985.18 ; v1@2093,1960.83 HC595B-4.15@2093,1984.19
  Bottom Layer w10: v1@1843,1961.82 v1(1843.38,1961.44) ; v1@2093,1960.83 v1(2093.38,1960.45)
2A4D: HC595B-3.15 LVC244A-3.16 | length 321.4
  Top Layer w5: v1(1283,1961.82) 1284.36,1960.45 1296.56,1960.45 1309.58,1947.44 1324.02,1947.44 1336.64,1934.82 1357.36,1934.82 1382.99,1960.45 v1(1533.38,1960.45) v1@1535.38,1960.45
  Bottom Layer w5: v1(1283,1961.82) LVC244A-3.16@1283,1985.18 ; v1@1533,1960.83 HC595B-3.15@1533,1984.19
  Bottom Layer w10: v1@1533,1960.83 v1(1533.38,1960.45)
2Y1A: LVC244A-1.8 RB1.1 | length 321.8
  Bottom Layer w5: LVC244A-1.8@253.02,2039.26 281.25,2039.26 305.31,2063.33 305.31,2158.31 316,2169 434,2169 439,2174 RB1.1@439,2198.38
2Y1B: LVC244A-2.8 RB2.1 | length 311.4
  Bottom Layer w5: LVC244A-2.8@812.02,2040.26 840.25,2040.26 850.38,2050.4 850.38,2139.57 872.2,2161.39 983.39,2161.39 997,2175 RB2.1@997,2193.38
2Y1C: LVC244A-4.8 RB4.1 | length 311.4
  Bottom Layer w5: LVC244A-4.8@1942.02,2036.26 1971.25,2036.26 1996,2061.02 1996,2150.19 2004.2,2158.39 2114.39,2158.39 2127,2171 RB4.1@2127,2189.38
2Y1D: LVC244A-3.8 RB3.1 | length 313.6
  Bottom Layer w5: LVC244A-3.8@1384.02,2037.26 1412.25,2037.26 1437.14,2062.15 1437.14,2137.45 1436,2138.59 1436,2150.19 1444.2,2158.39 1455.8,2158.39 1457.3,2156.89 1553.89,2156.89 1569,2172 RB3.1@1569,2190.38
2Y2A: LVC244A-1.6 RA1.1 | length 218.4
  Bottom Layer w5: LVC244A-1.6@231.37,2076.67 231.37,2101.37 323.38,2193.38 RA1.1@387,2193.38
2Y2B: LVC244A-2.6 RA2.1 | length 218.4
  Bottom Layer w5: LVC244A-2.6@789.37,2076.67 789.37,2101.37 881.38,2193.38 RA2.1@945,2193.38
2Y2C: LVC244A-4.6 RA4.1 | length 215.8
  Bottom Layer w5: LVC244A-4.6@1922.37,2074.11 1922.37,2100.37 2011.38,2189.38 RA4.1@2075,2189.38
2Y2D: LVC244A-3.6 RA3.1 | length 218.4
  Bottom Layer w5: LVC244A-3.6@1361.37,2073.67 1361.37,2098.37 1453.38,2190.38 RA3.1@1517,2190.38
2Y3A: LVC244A-1.4 RF1.1 | length 123.6
  Bottom Layer w5: LVC244A-1.4@199.87,2076.67 199.87,2107.87 219,2127 RF1.1@219,2192.38
2Y3B: LVC244A-2.4 RF2.1 | length 123.6
  Bottom Layer w5: LVC244A-2.4@757.87,2076.67 757.87,2107.87 777,2127 RF2.1@777,2192.38
2Y3C: LVC244A-4.4 RF4.1 | length 131.9
  Bottom Layer w5: LVC244A-4.4@1890.87,2074.11 1890.87,2152.87 1907,2169 RF4.1@1907,2199.38
2Y3D: LVC244A-3.4 RF3.1 | length 123.6
  Bottom Layer w5: LVC244A-3.4@1329.87,2073.67 1329.87,2104.87 1349,2124 RF3.1@1349,2189.38
2Y4A: LVC244A-1.2 RG1.1 | length 114.3
  Bottom Layer w5: LVC244A-1.2@168.38,2076.67 RG1.1@168.38,2191
2Y4B: LVC244A-2.2 RG2.1 | length 114.3
  Bottom Layer w5: LVC244A-2.2@726.38,2076.67 RG2.1@726.38,2191
2Y4C: LVC244A-4.2 RG4.1 | length 125.7
  Bottom Layer w5: RG4.1@1856,2198.38 1859.38,2195 LVC244A-4.2@1859.38,2074.11
2Y4D: LVC244A-3.2 RG3.1 | length 114.3
  Bottom Layer w5: LVC244A-3.2@1298.38,2073.67 RG3.1@1298.38,2188
GND: 7SEG1.3 7SEG1.8 7SEG2.3 7SEG2.8 7SEG3.3 7SEG3.8 7SEG4.3 7SEG4.8 C1.2 C2.2 C3.2 C4.2 C5.2 C6.2 C7.2 C8.2 C9.2 C10.2 C11.2 HC595-ROW.8 HC595-ROW.13 HC595-ROW.17 HC595B-1.8 HC595B-1.13 HC595B-1.17 HC595B-2.8 HC595B-2.13 HC595B-2.17 HC595B-3.8 HC595B-3.13 HC595B-3.17 HC595B-4.8 HC595B-4.13 HC595B-4.17 HC595B-COLUMN.8 HC595B-COLUMN.13 HC595B-COLUMN.17 I2C1.1 I2C2.1 J4.20 LVC244A-1.9 LVC244A-1.21 LVC244A-2.9 LVC244A-2.21 LVC244A-3.9 LVC244A-3.21 LVC244A-4.9 LVC244A-4.21 LVC244A-COLUMN.9 LVC244A-COLUMN.18 LVC244A-COLUMN.20 LVC244A-COLUMN.21 | length 3160.4
  Top Layer w6: HC595B-COLUMN.13@102.72,1402.62 124.38,1402.62 ; v1(117,2110.77) 143.69,2110.77 180.31,2147.39 v1(320,2147.39) ; v3(148,1379) 124.38,1402.62 ; HC595B-COLUMN.8@193.28,1402.62 124.38,1402.62 ; 519.38,1321 v2(532,1321) ; v1(676,2113) 703.92,2113 738.31,2147.39 v1(878,2147.39) ; v1(1245.23,2112) 1284,2112 1316.39,2144.39 v1(1450,2144.39) ; 7SEG3.8@1432.4,2322.42 7SEG3.8@1450,2304.82 ; v1(1805,2107.77) 1833.69,2107.77 1870.31,2144.39 v1(2010,2144.39) ; HC595-ROW.8@2030.62,1175.72 2030.62,1197.38 v3(2007,1221) 2030.62,1244.62 HC595-ROW.13@2030.62,1266.28
  Top Layer w10: v2(90,1501) 90,1415.35 HC595B-COLUMN.13@102.72,1402.62 ; C10.2@467.97,1372.41 519.38,1321
  Bottom Layer w5: LVC244A-COLUMN.21@407.56,1382.87 v3(415.44,1375) ; 431.62,2004.21 408,2027.83 HC595B-1.17@431.62,2051.45 ; 992.62,2008.21 969,2031.83 HC595B-2.17@992.62,2055.45 ; C4.2@1049,2149.39 C4.2@1049,2153.01 ; 1564.62,2005.21 1541,2028.83 1564.62,2052.45 ; C6.2@1621,2146.39 C6.2@1621,2150.01 ; 2124.62,2005.21 v3(2101,2028.83) 2124.62,2052.45 ; C8.2@2181,2146.39 C8.2@2181,2150.01
  Bottom Layer w6: LVC244A-1.21@228.43,2023.96 283.57,2023.96 320,2060.39 v1(320,2147.39) ; LVC244A-COLUMN.9@381.97,1382.87 LVC244A-COLUMN.21@407.56,1382.87 ; HC595B-1.13@431.62,1982.56 431.62,2004.21 ; HC595B-1.17@431.62,2051.45 431.62,2097.8 C2.2@486.83,2153.01 ; LVC244A-COLUMN.21@443,1375 466.62,1351.37 LVC244A-COLUMN.20@504.02,1351.37 522.63,1351.37 532,1342 v2(532,1321) ; LVC244A-COLUMN.21@470.56,1382.87 LVC244A-COLUMN.18@504.02,1382.87 ; LVC244A-2.21@786.43,2023.96 841.57,2023.96 878,2060.39 v1(878,2147.39) ; HC595B-2.13@992.62,1986.56 992.62,2008.21 ; HC595B-2.8@993.62,2078.67 993.62,2102.63 C4.2@1048,2157.01 ; LVC244A-3.21@1322,2029.39 v3(1349.56,2029.39) 1350,2029.39 1357.88,2021.52 LVC244A-3.9@1383.02,2021.52 1414.13,2021.52 1450,2057.39 v1(1450,2144.39) ; HC595B-3.13@1564.62,1983.56 1564.62,2005.21 ; 1564.62,2052.45 1564.62,2098.8 C6.2@1619.83,2154.01 ; LVC244A-4.21@1918.43,2020.96 LVC244A-4.9@1944.02,2020.96 1973.57,2020.96 2010,2057.39 v1(2010,2144.39) ; HC595B-4.13@2124.62,1983.56 2124.62,2005.21 ; 2124.62,2052.45 HC595B-4.8@2124.62,2074.11 2124.62,2090.01 C8.2@2181,2146.39
  other v2: 1775,107 1823,107 1869,107 1318,188 1343,212 139,827 101,859 139,859 489,1139 522,1140 553,1140 2114,1390 2081,1445 2138,1447 139,1545
  other v3: 415.44,1375 470.56,1375 1294.44,2029.39 1294.44,2029.39 1855.44,2028.83 1855.44,2028.83 1910.56,2028.83 1910.56,2028.83 2101,2028.83 409,2030.39 164.44,2031.39 164.44,2031.39 219.56,2031.39 219.56,2031.39 723.44,2032.39 723.44,2032.39 778.56,2032.39 778.56,2032.39 1540.83,2032.39 1540.83,2032.39 970,2033.39 970,2033.39
  other v4: 1669.79,1841.01 517.79,1937.01 1084,1953 1688,2114 583.79,2139.01 1149,2153
Net7SEG1_1: 7SEG1.1 RE1.2 | length 119.2
  Bottom Layer w5: RE1.2@97,1834.38 97,1726.55 7SEG1.1@105.06,1718.49
Net7SEG1_2: 7SEG1.2 RD1.2 | length 137.9
  Bottom Layer w5: RD1.2@152,1834.38 152,1771.55 7SEG1.2@205.06,1718.49
Net7SEG1_4: 7SEG1.4 RC1.2 | length 115
  Bottom Layer w5: 7SEG1.4@406,1719.42 RC1.2@406,1834.38
Net7SEG1_5: 7SEG1.5 RDP1.2 | length 135
  Bottom Layer w5: RDP1.2@459,1834.38 459,1764.55 7SEG1.5@505.06,1718.49
Net7SEG1_6: 7SEG1.6 RB1.2 | length 118.3
  Bottom Layer w5: RB1.2@439,2240.62 439,2272 489.42,2322.42 7SEG1.6@505.06,2322.42
Net7SEG1_7: 7SEG1.7 RA1.2 | length 89.3
  Bottom Layer w5: RA1.2@387,2240.62 387,2304.36 7SEG1.7@405.06,2322.42
Net7SEG1_9: 7SEG1.9 RF1.2 | length 88.6
  Bottom Layer w5: 7SEG1.9@205.06,2322.42 219,2308.49 RF1.2@219,2239.62
Net7SEG1_10: 7SEG1.10 RG1.2 | length 125
  Bottom Layer w5: 7SEG1.10@105.06,2322.42 105.06,2270.94 135.38,2240.62 RG1.2@166,2240.62
Net7SEG2_1: 7SEG2.1 RE2.2 | length 129.8
  Bottom Layer w5: RE2.2@657,1843.38 657,1730.22 7SEG2.1@668.73,1718.49
Net7SEG2_2: 7SEG2.2 RD2.2 | length 150.6
  Bottom Layer w5: RD2.2@709,1844.38 709,1778.22 7SEG2.2@768.73,1718.49
Net7SEG2_4: 7SEG2.4 RC2.2 | length 114.2
  Bottom Layer w5: 7SEG2.4@963,1724.22 RC2.2@963,1838.38
Net7SEG2_5: 7SEG2.5 RDP2.2 | length 142.9
  Bottom Layer w5: RDP2.2@1018,1840.38 1018,1769.22 7SEG2.5@1068.73,1718.49
Net7SEG2_6: 7SEG2.6 RB2.2 | length 120.4
  Bottom Layer w5: RB2.2@999,2241.62 999,2271 1050.42,2322.42 7SEG2.6@1068.73,2322.42
Net7SEG2_7: 7SEG2.7 RA2.2 | length 88.4
  Bottom Layer w5: RA2.2@948,2242.62 948,2301.69 7SEG2.7@968.73,2322.42
Net7SEG2_9: 7SEG2.9 RF2.2 | length 83.2
  Bottom Layer w5: 7SEG2.9@768.73,2322.42 777,2314.15 RF2.2@777,2242.62
Net7SEG2_10: 7SEG2.10 RG2.2 | length 117.8
  Bottom Layer w5: 7SEG2.10@668.73,2322.42 668.73,2275.51 701.62,2242.62 RG2.2@726,2242.62
Net7SEG3_1: 7SEG3.1 RE3.2 | length 121.5
  Bottom Layer w5: 7SEG3.1@1228,1722.88 RE3.2@1228,1844.38
Net7SEG3_2: 7SEG3.2 RD3.2 | length 148.6
  Bottom Layer w5: RD3.2@1280,1845.38 1280,1770.88 7SEG3.2@1332.4,1718.49
Net7SEG3_4: 7SEG3.4 RC3.2 | length 114.3
  Bottom Layer w5: 7SEG3.4@1536,1722.09 RC3.2@1536,1836.38
Net7SEG3_5: 7SEG3.5 RDP3.2 | length 135.9
  Bottom Layer w5: RDP3.2@1589,1836.38 1589,1761.88 7SEG3.5@1632.4,1718.49
Net7SEG3_6: 7SEG3.6 RB3.2 | length 115.7
  Bottom Layer w5: RB3.2@1570,2239.62 1570,2272 1620.42,2322.42 7SEG3.6@1632.4,2322.42
Net7SEG3_7: 7SEG3.7 RA3.2 | length 87.9
  Bottom Layer w5: RA3.2@1520,2239.62 1520,2310.03 7SEG3.7@1532.4,2322.42
Net7SEG3_9: 7SEG3.9 RF3.2 | length 85.5
  Bottom Layer w5: 7SEG3.9@1332.4,2322.42 1351,2303.82 RF3.2@1351,2244.62
Net7SEG3_10: 7SEG3.10 RG3.2 | length 116.1
  Bottom Layer w5: 7SEG3.10@1232.4,2322.42 1232.4,2295.6 1282.38,2245.62 RG3.2@1301,2245.62
Net7SEG4_1: 7SEG4.1 RE4.2 | length 118.8
  Bottom Layer w5: 7SEG4.1@1787,1727.55 RE4.2@1787,1846.38
Net7SEG4_2: 7SEG4.2 RD4.2 | length 150.7
  Bottom Layer w5: RD4.2@1841,1846.38 1841,1773.55 7SEG4.2@1896.06,1718.49
Net7SEG4_4: 7SEG4.4 RC4.2 | length 114.8
  Bottom Layer w5: 7SEG4.4@2095,1719.55 RC4.2@2095,1834.38
Net7SEG4_5: 7SEG4.5 RDP4.2 | length 136.2
  Bottom Layer w5: RDP4.2@2147,1834.38 2147,1767.55 7SEG4.5@2196.06,1718.49
Net7SEG4_6: 7SEG4.6 RB4.2 | length 116.4
  Bottom Layer w5: RB4.2@2128,2241.62 2128,2267 2183.42,2322.42 7SEG4.6@2196.06,2322.42
Net7SEG4_7: 7SEG4.7 RA4.2 | length 89.1
  Bottom Layer w5: RA4.2@2076,2241.62 2076,2302.36 7SEG4.7@2096.06,2322.42
Net7SEG4_9: 7SEG4.9 RF4.2 | length 84.3
  Bottom Layer w5: 7SEG4.9@1896.06,2322.42 1907,2311.49 RF4.2@1907,2242.62
Net7SEG4_10: 7SEG4.10 RG4.2 | length 118.9
  Bottom Layer w5: 7SEG4.10@1796.06,2322.42 1796.06,2278.18 1831.62,2242.62 RG4.2@1856,2242.62
NetD1A_1: D1A.1 R1A.1
  other v1: 729.11,1397.57
NetD1B_1: D1B.1 R1B.1
  other v1: 846.03,1397.57
NetD1C_1: D1C.1 R1C.1
  other v1: 971.31,1402.58
NetD1D_1: D1D.1 R1D.1
  other v1: 1095.24,1397.57
NetD1E_1: D1E.1 R1E.1
  other v1: 1221.32,1404
NetD1F_1: D1F.1 R1F.1
  other v1: 1343.77,1397.57
NetD1G_1: D1G.1 R1G.1
  other v1: 1468.18,1401
NetD1H_1: D1H.1 R1H.1
  other v1: 1590.19,1399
